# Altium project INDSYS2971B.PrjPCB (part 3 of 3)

## Sheet INDSYS2971B_DAC.SchDoc
size 431 x 279 mm; Date: Not shown in title block; ApprovedBy: Not shown in title block; CheckedBy: Not shown in title block; Author: Not shown in title block; CompanyName: Not shown in title block; Engineer: Not shown in title block; Organization: Not shown in title block; Address1: Not shown in title block; Address2: Not shown in title block; Address3: Not shown in title block; Address4: Not shown in title block; DocumentNumber: 8; Revision: Use project parameter SCH_Rev; SheetNumber: 8; SheetTotal: 11; PageSetup: Record=PageOptions¦CenterHorizontal=True¦CenterVertical=True¦PrintScale=1.00¦XCorrection=1.00¦YCorrection=1.00¦PrintKind=0¦BorderSize=5000000¦LeftOffset=0¦BottomOffset=0¦Orientation=2¦PaperLength=1000¦PaperWidth=1000¦Scale=100¦PaperSource=15¦PrintQuality=600¦MediaType=1¦DitherType=10¦PaperKind=Letter¦PrintScaleMode=1
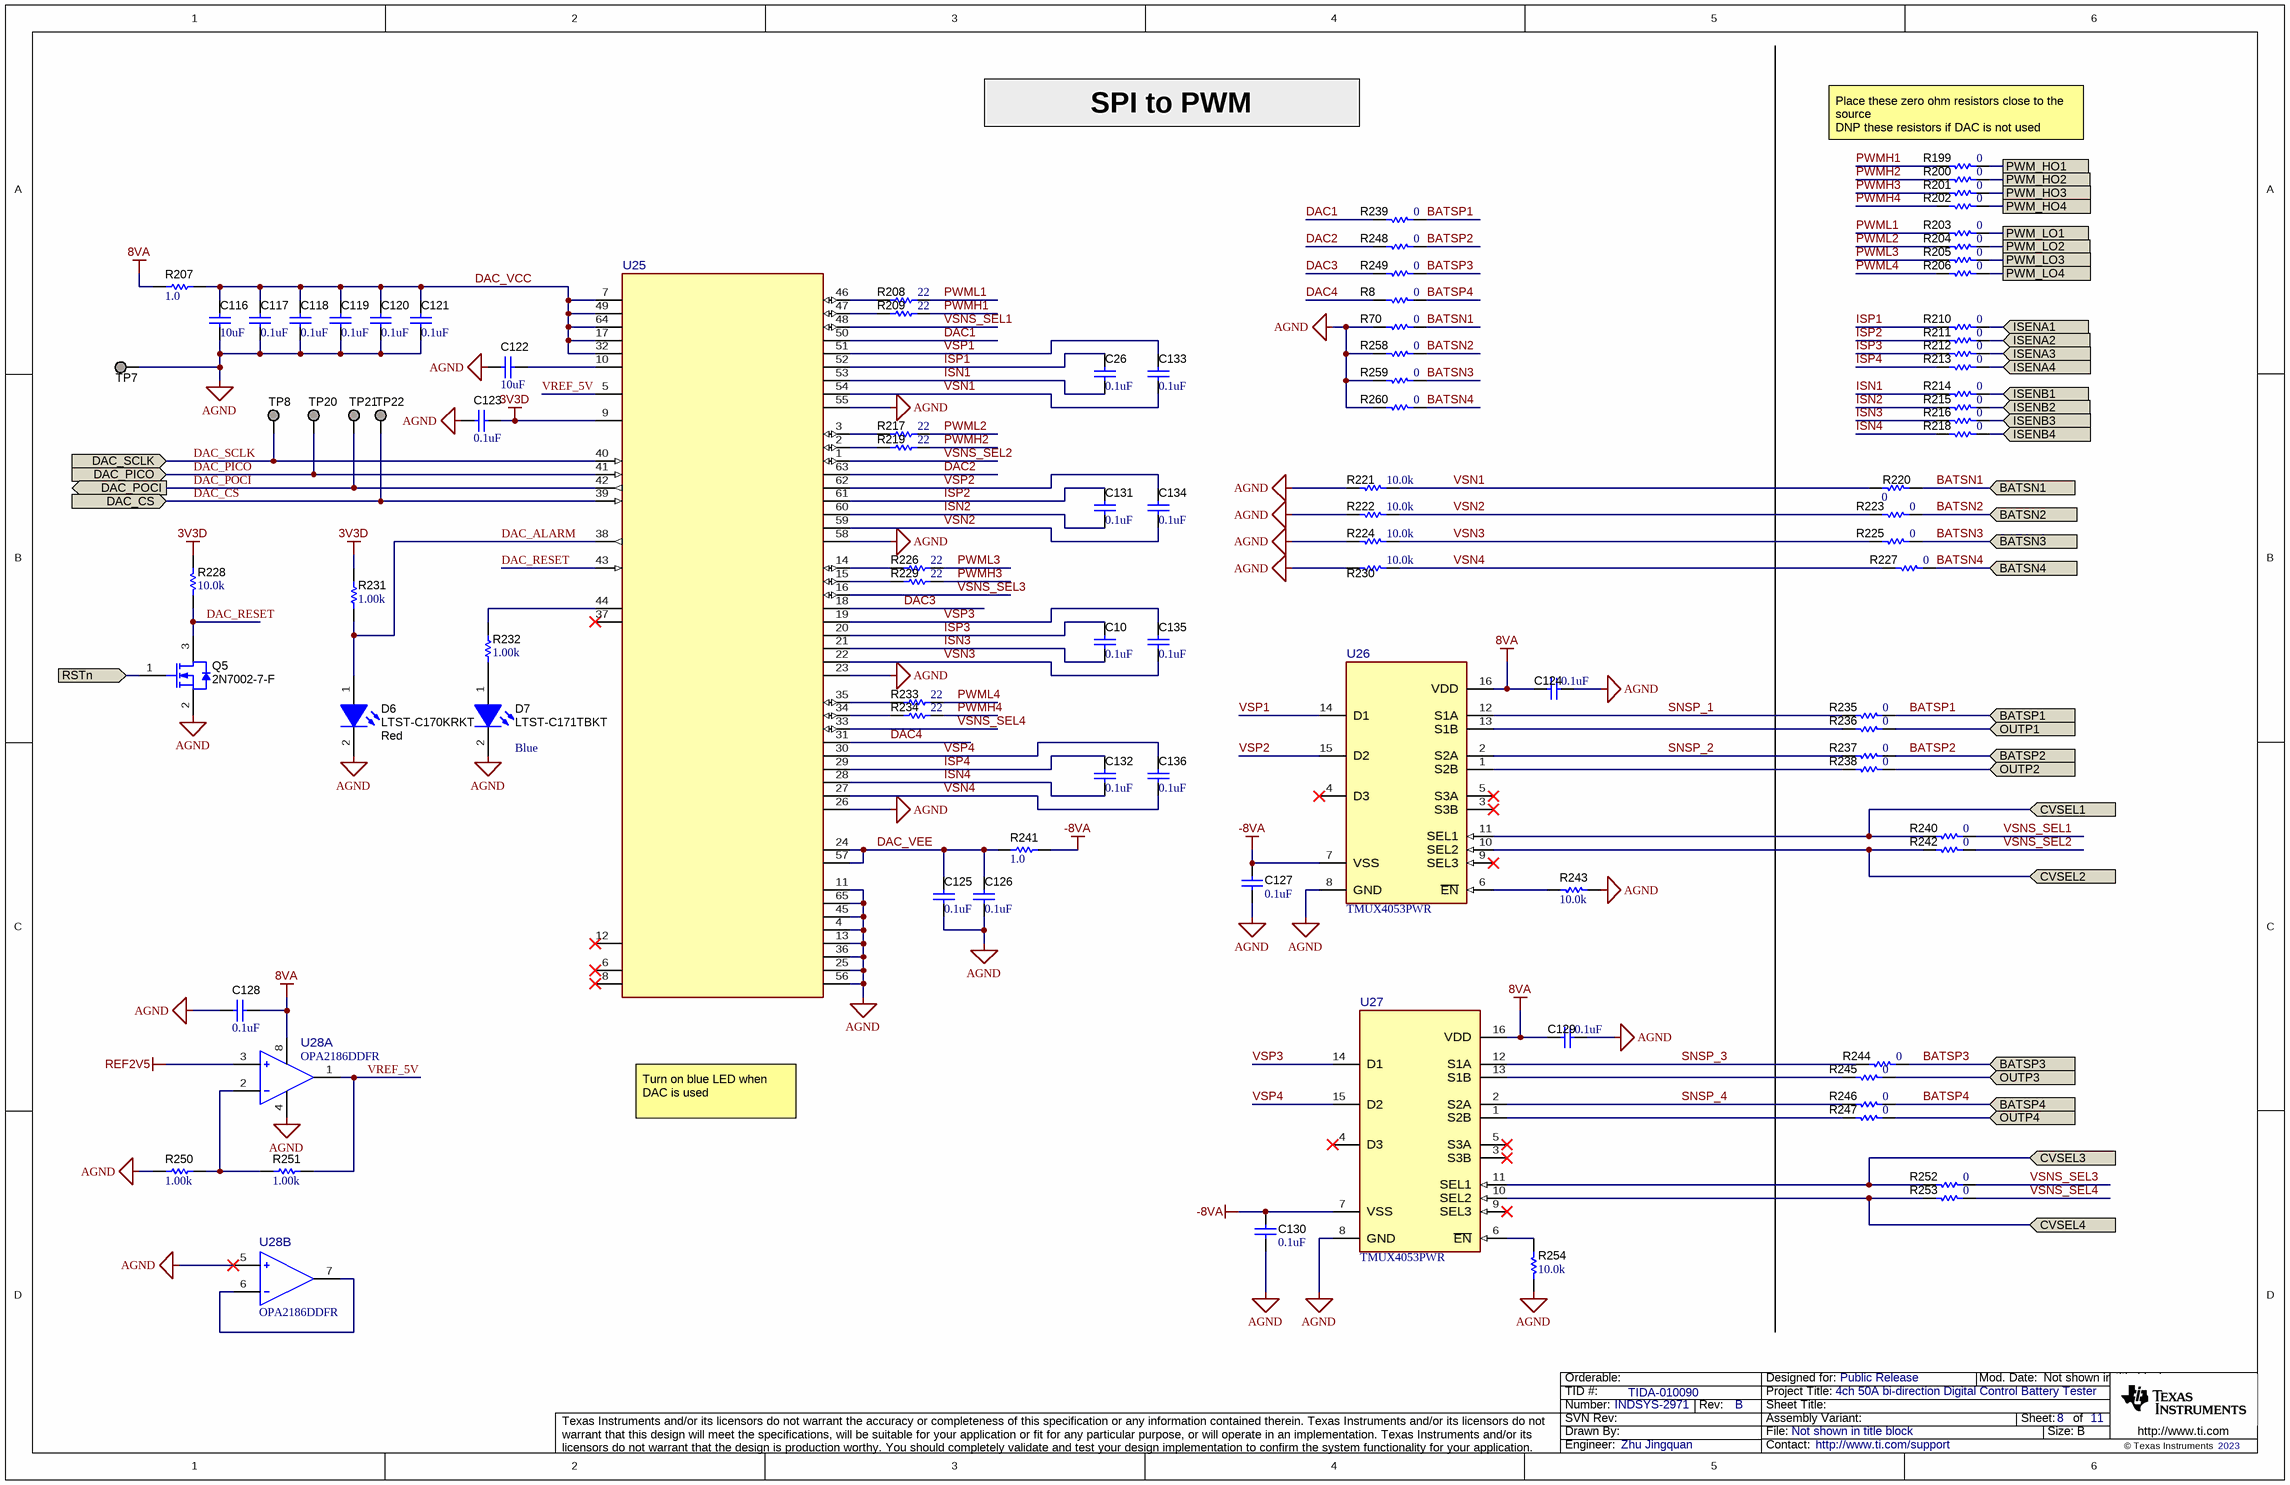
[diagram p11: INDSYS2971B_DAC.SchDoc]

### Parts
C10  ValueDisplayed: 0.1uF  [0402]  (hidden comment: GRM155R61C104KA88D)
C26  ValueDisplayed: 0.1uF  [0402]  (hidden comment: GRM155R61C104KA88D)
C116  ValueDisplayed: 10uF  [0603]  (hidden comment: GRM188R61E106MA73D)
C117  ValueDisplayed: 0.1uF  [0402]  (hidden comment: GRM155R61C104KA88D)
C118  ValueDisplayed: 0.1uF  [0402]  (hidden comment: GRM155R61C104KA88D)
C119  ValueDisplayed: 0.1uF  [0402]  (hidden comment: GRM155R61C104KA88D)
C120  ValueDisplayed: 0.1uF  [0402]  (hidden comment: GRM155R61C104KA88D)
C121  ValueDisplayed: 0.1uF  [0402]  (hidden comment: GRM155R61C104KA88D)
C122  ValueDisplayed: 10uF  [0603]  (hidden comment: GRM188R61E106MA73D)
C123  ValueDisplayed: 0.1uF  [0402]  (hidden comment: GRM155R61C104KA88D)
C124  ValueDisplayed: 0.1uF  [0402]  (hidden comment: GRM155R61C104KA88D)
C125  ValueDisplayed: 0.1uF  [0402]  (hidden comment: GRM155R61C104KA88D)
C126  ValueDisplayed: 0.1uF  [0402]  (hidden comment: GRM155R61C104KA88D)
C127  ValueDisplayed: 0.1uF  [0402]  (hidden comment: GRM155R61C104KA88D)
C128  ValueDisplayed: 0.1uF  [0402]  (hidden comment: GRM155R61C104KA88D)
C129  ValueDisplayed: 0.1uF  [0402]  (hidden comment: GRM155R61C104KA88D)
C130  ValueDisplayed: 0.1uF  [0402]  (hidden comment: GRM155R61C104KA88D)
C131  ValueDisplayed: 0.1uF  [0402]  (hidden comment: GRM155R61C104KA88D)
C132  ValueDisplayed: 0.1uF  [0402]  (hidden comment: GRM155R61C104KA88D)
C133  ValueDisplayed: 0.1uF  [0402]  (hidden comment: GRM155R61C104KA88D)
C134  ValueDisplayed: 0.1uF  [0402]  (hidden comment: GRM155R61C104KA88D)
C135  ValueDisplayed: 0.1uF  [0402]  (hidden comment: GRM155R61C104KA88D)
C136  ValueDisplayed: 0.1uF  [0402]  (hidden comment: GRM155R61C104KA88D)
D6  LTST-C170KRKT  value Red  [LED_LTST-C170_Red]
D7  LTST-C171TBKT  value Blue  [LTST-C171_Blue]
Q5  2N7002-7-F  [SOT-23]
R8  ValueDisplayed: 0  [0402]  (hidden comment: CRCW04020000Z0ED)
R70  ValueDisplayed: 0  [0402]  (hidden comment: CRCW04020000Z0ED)
R199  ValueDisplayed: 0  [0402]  (hidden comment: CRCW04020000Z0ED)
R200  ValueDisplayed: 0  [0402]  (hidden comment: CRCW04020000Z0ED)
R201  ValueDisplayed: 0  [0402]  (hidden comment: CRCW04020000Z0ED)
R202  ValueDisplayed: 0  [0402]  (hidden comment: CRCW04020000Z0ED)
R203  ValueDisplayed: 0  [0402]  (hidden comment: CRCW04020000Z0ED)
R204  ValueDisplayed: 0  [0402]  (hidden comment: CRCW04020000Z0ED)
R205  ValueDisplayed: 0  [0402]  (hidden comment: CRCW04020000Z0ED)
R206  ValueDisplayed: 0  [0402]  (hidden comment: CRCW04020000Z0ED)
R207  ValueDisplayed: 1.0  [0603]  (hidden comment: CRCW06031R00JNEA)
R208  ValueDisplayed: 22  [0402]  (hidden comment: CRCW040222R0JNED)
R209  ValueDisplayed: 22  [0402]  (hidden comment: CRCW040222R0JNED)
R210  ValueDisplayed: 0  [0402]  (hidden comment: CRCW04020000Z0ED)
R211  ValueDisplayed: 0  [0402]  (hidden comment: CRCW04020000Z0ED)
R212  ValueDisplayed: 0  [0402]  (hidden comment: CRCW04020000Z0ED)
R213  ValueDisplayed: 0  [0402]  (hidden comment: CRCW04020000Z0ED)
R214  ValueDisplayed: 0  [0402]  (hidden comment: CRCW04020000Z0ED)
R215  ValueDisplayed: 0  [0402]  (hidden comment: CRCW04020000Z0ED)
R216  ValueDisplayed: 0  [0402]  (hidden comment: CRCW04020000Z0ED)
R217  ValueDisplayed: 22  [0402]  (hidden comment: CRCW040222R0JNED)
R218  ValueDisplayed: 0  [0402]  (hidden comment: CRCW04020000Z0ED)
R219  ValueDisplayed: 22  [0402]  (hidden comment: CRCW040222R0JNED)
R220  ValueDisplayed: 0  [0402]  (hidden comment: CRCW04020000Z0ED)
R221  ValueDisplayed: 10.0k  [0402]  (hidden comment: PCF0402-12-10K0BT1)
R222  ValueDisplayed: 10.0k  [0402]  (hidden comment: PCF0402-12-10K0BT1)
R223  ValueDisplayed: 0  [0402]  (hidden comment: CRCW04020000Z0ED)
R224  ValueDisplayed: 10.0k  [0402]  (hidden comment: PCF0402-12-10K0BT1)
R225  ValueDisplayed: 0  [0402]  (hidden comment: CRCW04020000Z0ED)
R226  ValueDisplayed: 22  [0402]  (hidden comment: CRCW040222R0JNED)
R227  ValueDisplayed: 0  [0402]  (hidden comment: CRCW04020000Z0ED)
R228  ValueDisplayed: 10.0k  [0402]  (hidden comment: PCF0402-12-10K0BT1)
R229  ValueDisplayed: 22  [0402]  (hidden comment: CRCW040222R0JNED)
R230  ValueDisplayed: 10.0k  [0402]  (hidden comment: PCF0402-12-10K0BT1)
R231  ValueDisplayed: 1.00k  [0402]  (hidden comment: ERA-2AEB102X)
R232  ValueDisplayed: 1.00k  [0402]  (hidden comment: ERA-2AEB102X)
R233  ValueDisplayed: 22  [0402]  (hidden comment: CRCW040222R0JNED)
R234  ValueDisplayed: 22  [0402]  (hidden comment: CRCW040222R0JNED)
R235  ValueDisplayed: 0  [0402]  (hidden comment: CRCW04020000Z0ED)
R236  ValueDisplayed: 0  [0402]  (hidden comment: CRCW04020000Z0ED)
R237  ValueDisplayed: 0  [0402]  (hidden comment: CRCW04020000Z0ED)
R238  ValueDisplayed: 0  [0402]  (hidden comment: CRCW04020000Z0ED)
R239  ValueDisplayed: 0  [0402]  (hidden comment: CRCW04020000Z0ED)
R240  ValueDisplayed: 0  [0402]  (hidden comment: CRCW04020000Z0ED)
R241  ValueDisplayed: 1.0  [0603]  (hidden comment: CRCW06031R00JNEA)
R242  ValueDisplayed: 0  [0402]  (hidden comment: CRCW04020000Z0ED)
R243  ValueDisplayed: 10.0k  [0402]  (hidden comment: PCF0402-12-10K0BT1)
R244  ValueDisplayed: 0  [0402]  (hidden comment: CRCW04020000Z0ED)
R245  ValueDisplayed: 0  [0402]  (hidden comment: CRCW04020000Z0ED)
R246  ValueDisplayed: 0  [0402]  (hidden comment: CRCW04020000Z0ED)
R247  ValueDisplayed: 0  [0402]  (hidden comment: CRCW04020000Z0ED)
R248  ValueDisplayed: 0  [0402]  (hidden comment: CRCW04020000Z0ED)
R249  ValueDisplayed: 0  [0402]  (hidden comment: CRCW04020000Z0ED)
R250  ValueDisplayed: 1.00k  [0402]  (hidden comment: ERA-2AEB102X)
R251  ValueDisplayed: 1.00k  [0402]  (hidden comment: ERA-2AEB102X)
R252  ValueDisplayed: 0  [0402]  (hidden comment: CRCW04020000Z0ED)
R253  ValueDisplayed: 0  [0402]  (hidden comment: CRCW04020000Z0ED)
R254  ValueDisplayed: 10.0k  [0402]  (hidden comment: PCF0402-12-10K0BT1)
R258  ValueDisplayed: 0  [0402]  (hidden comment: CRCW04020000Z0ED)
R259  ValueDisplayed: 0  [0402]  (hidden comment: CRCW04020000Z0ED)
R260  ValueDisplayed: 0  [0402]  (hidden comment: CRCW04020000Z0ED)
TP7  5019  [Keystone_5019]  (value not drawn)
TP8  5019  [Keystone_5019]  (value not drawn)
TP20  5019  [Keystone_5019]  (value not drawn)
TP21  5019  [Keystone_5019]  (value not drawn)
TP22  5019  [Keystone_5019]  (value not drawn)
U25  (no value)  [RGC0064P-MFG]
U26  TMUX4053PWR  [PW0016A-MFG]
U27  TMUX4053PWR  [PW0016A-MFG]
U28  OPA2186DDFR  [DDF0008A-MFG]  (parts A,B of 2)

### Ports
BATSN1 (in), BATSN2 (in), BATSN3 (in), BATSN4 (in), BATSP1 (in), BATSP2 (in), BATSP3 (in), BATSP4 (in), CVSEL1 (in), CVSEL2 (in), CVSEL3 (in), CVSEL4 (in), DAC_CS (in), DAC_PICO (in), DAC_POCI (out), DAC_SCLK (in), ISENA1 (in), ISENA2 (in), ISENA3 (in), ISENA4 (in), ISENB1 (in), ISENB2 (in), ISENB3 (in), ISENB4 (in), OUTP1 (in), OUTP2 (in), OUTP3 (in), OUTP4 (in), PWM_HO1, PWM_HO2, PWM_HO3, PWM_HO4, PWM_LO1, PWM_LO2, PWM_LO3, PWM_LO4, RSTn (in)

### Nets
3V3D: C123.2 R228.2 R231.2 U25.9(NC)
8VA: C124.2 C128.1 C129.2 R207.1 U26.16(VDD) U27.16(VDD) U28.8(V+)
-8VA: C127.2 C130.2 R241.2 U26.7(VSS) U27.7(VSS)
AGND: C116.2 C117.1 C118.1 C119.1 C120.1 C121.1 C122.1 C123.1 C124.1 C125.1 C126.1 C127.1 C128.2 C129.1 C130.1 D6.2(K) D7.2(K) Q5.2(S) R70.2 R221.1 R222.1 R224.1 R230.1 R243.1 R250.1 R254.1 R258.2 R259.2 R260.2 TP7.1 U25.4(NC) U25.11(NC) U25.13(NC) U25.23(NC) U25.25(NC) U25.26(NC) U25.36(NC) U25.45(NC) U25.55(NC) U25.56(NC) U25.58(NC) U25.65(NC) U26.8(GND) U27.8(GND) U28.4(V-) U28.5(+IN_B)
REF2V5: U28.3(+IN_A)
BATSN1: R70.1 R220.1 ; port BATSN1
BATSN2: R223.1 R258.1 ; port BATSN2
BATSN3: R225.1 R259.1 ; port BATSN3
BATSN4: R227.1 R260.1 ; port BATSN4
BATSP1: R235.1 R239.1 ; port BATSP1
BATSP2: R237.1 R248.1 ; port BATSP2
BATSP3: R244.1 R249.1 ; port BATSP3
BATSP4: R8.1 R246.1 ; port BATSP4
CVSEL1: R240.2 U26.11(SEL1) ; port CVSEL1
CVSEL2: R242.2 U26.10(SEL2) ; port CVSEL2
CVSEL3: R252.2 U27.11(SEL1) ; port CVSEL3
CVSEL4: R253.2 U27.10(SEL2) ; port CVSEL4
DAC1: R239.2 U25.50(NC)
DAC2: R248.2 U25.63(NC)
DAC3: R249.2 U25.18(NC)
DAC4: R8.2 U25.31(NC)
DAC_ALARM: D6.1(A) R231.1 U25.38(NC)
DAC_CS: TP22.1 U25.39(NC) ; port DAC_CS
DAC_PICO: TP20.1 U25.41(NC) ; port DAC_PICO
DAC_POCI: TP21.1 U25.42(NC) ; port DAC_POCI
DAC_RESET: Q5.3(D) R228.1 U25.43(NC)
DAC_SCLK: TP8.1 U25.40(NC) ; port DAC_SCLK
DAC_VCC: C116.1 C117.2 C118.2 C119.2 C120.2 C121.2 R207.2 U25.7(NC) U25.17(NC) U25.32(NC) U25.49(NC) U25.64(NC)
DAC_VEE: C125.2 C126.2 R241.1 U25.24(NC) U25.57(NC)
ISENA1: R210.1 ; port ISENA1
ISENA2: R211.1 ; port ISENA2
ISENA3: R212.1 ; port ISENA3
ISENA4: R213.1 ; port ISENA4
ISENB1: R214.1 ; port ISENB1
ISENB2: R215.1 ; port ISENB2
ISENB3: R216.1 ; port ISENB3
ISENB4: R218.1 ; port ISENB4
ISN1: C26.1 R214.2 U25.53(NC)
ISN2: C131.1 R215.2 U25.60(NC)
ISN3: C10.1 R216.2 U25.21(NC)
ISN4: C132.1 R218.2 U25.28(NC)
ISP1: C26.2 R210.2 U25.52(NC)
ISP2: C131.2 R211.2 U25.61(NC)
ISP3: C10.2 R212.2 U25.20(NC)
ISP4: C132.2 R213.2 U25.29(NC)
OUTP1: R236.1 ; port OUTP1
OUTP2: R238.1 ; port OUTP2
OUTP3: R245.1 ; port OUTP3
OUTP4: R247.1 ; port OUTP4
PWM_HO1: R199.1 ; port PWM_HO1
PWM_HO2: R200.1 ; port PWM_HO2
PWM_HO3: R201.1 ; port PWM_HO3
PWM_HO4: R202.1 ; port PWM_HO4
PWM_LO1: R203.1 ; port PWM_LO1
PWM_LO2: R204.1 ; port PWM_LO2
PWM_LO3: R205.1 ; port PWM_LO3
PWM_LO4: R206.1 ; port PWM_LO4
PWMH1: R199.2 R209.2
PWMH2: R200.2 R219.2
PWMH3: R201.2 R229.2
PWMH4: R202.2 R234.2
PWML1: R203.2 R208.2
PWML2: R204.2 R217.2
PWML3: R205.2 R226.2
PWML4: R206.2 R233.2
RSTn: Q5.1(G) ; port RSTn
SNSP_1: R235.2 U26.12(S1A)
SNSP_2: R237.2 U26.2(S2A)
SNSP_3: R244.2 U27.12(S1A)
SNSP_4: R246.2 U27.2(S2A)
VREF_5V: R251.2 U25.5(NC) U28.1(OUT_A)
VSN1: C133.1 R220.2 R221.2 U25.54(NC)
VSN2: C134.1 R222.2 R223.2 U25.59(NC)
VSN3: C135.1 R224.2 R225.2 U25.22(NC)
VSN4: C136.1 R227.2 R230.2 U25.27(NC)
VSNS_SEL1: R240.1 U25.48(NC)
VSNS_SEL2: R242.1 U25.1(HARTB/GPIO2B)
VSNS_SEL3: R252.1 U25.16(NC)
VSNS_SEL4: R253.1 U25.33(NC)
VSP1: C133.2 U25.51(NC) U26.14(D1)
VSP2: C134.2 U25.62(NC) U26.15(D2)
VSP3: C135.2 U25.19(NC) U27.14(D1)
VSP4: C136.2 U25.30(NC) U27.15(D2)
NetC122_2: C122.2 U25.10(NC)
NetD7_1: D7.1(A) R232.1
NetR208_1: R208.1 U25.46(NC)
NetR209_1: R209.1 U25.47(NC)
NetR217_1: R217.1 U25.3(GPIO0B)
NetR219_1: R219.1 U25.2(PPCB/GPIO1B)
NetR226_1: R226.1 U25.14(NC)
NetR229_1: R229.1 U25.15(NC)
NetR232_2: R232.2 U25.44(NC)
NetR233_1: R233.1 U25.35(NC)
NetR234_1: R234.1 U25.34(NC)
NetR236_2: R236.2 U26.13(S1B)
NetR238_2: R238.2 U26.1(S2B)
NetR243_2: R243.2 U26.6(~{EN})
NetR245_2: R245.2 U27.13(S1B)
NetR247_2: R247.2 U27.1(S2B)
NetR250_2: R250.2 R251.1 U28.2(-IN_A)
NetR254_2: R254.2 U27.6(~{EN})
NetU28_6: U28.6(-IN_B) U28.7(OUT_B)

Not connected (* = marked no-connect by the designer): U25 6(NC)* 8(NC)* 12(NC)* 37(NC)*; U26 3(S3B)* 4(D3)* 5(S3A)* 9(SEL3)*; U27 3(S3B)* 4(D3)* 5(S3A)* 9(SEL3)*

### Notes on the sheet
- SPI to PWM
- Place these zero ohm resistors close to the source
  DNP these resistors if DAC is not used
- Turn on blue LED when DAC is used

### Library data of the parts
C10 C26 C117-C121 C123-C136 = CMP-0006591-2: CAP, CERM, 0.1 uF, 16 V, +/- 10%, X5R, 0402; Manufacturer: MuRata; TaMin_C: -55°C; Polarized: N; SizeAreaWB_mm2: 3; Value1: Unknown; U/M: EA; Value: 0.1uF; TaMax_C: 85°C; SizeZ_mm: 0.6; SizeX_mm: 1; SizeY_mm: 0.5; Value2: 16V; Cap_F: 100nF; AEC Category: Q200
C116 C122 = CMP-0007344-5: CAP, CERM, 10 uF, 25 V, +/- 20%, X5R, 0603; Manufacturer: MuRata; Polarized: N; Value: 10uF; U/M: EA; Cap_F: 10µF; Value1: Unknown; VDC_V: 25V; TaMin_C: -55°C; TaMax_C: 85°C; SizeArea_mm2: 1.28; SizeAreaWB_mm2: 4.68; SizeX_mm: 1.6; SizeY_mm: 0.8; SizeZ_mm: 1; AEC Category: Q200
D6 = CMP-0002829-3: LED, Red, SMD; Manufacturer: Lite-On; SizeZ_mm: 1.2; Value1: W; SizeY_mm: 1.25; Value2: 2V; SizeArea_mm2: 2.5; SizeX_mm: 2; SizeAreaWB_mm2: 6.75; Io_A: 20mA; Type: AlInGaP
D7 = CMP-0082437-2: LED, Blue, SMD; Manufacturer: Lite-On; Vr_V: 5V; SizeArea_mm2: 2.5; SizeAreaWB_mm2: 6.75; Io_A: 20mA; Green_Lifecycle: Not Set; Angle: 130; Value1: 0.076W; Type: InGaN; SizeY_mm: 1.25; Ir_A: 10µA; Power_TotalModule: 76mW; Value2: 3.3V; Green_REACh: Incomplete; SizeX_mm: 2; SizeZ_mm: 0.9
Q5 = CMP-0000769-1: MOSFET, N-CH, 60 V, 0.17 A, SOT-23; Alternate Manufacturer: None; Manufacturer: Diodes Inc.; SizeZ_mm: 1.1; ChType: N; Value2: 223 nC; Value1: 7; VdsMax_V: 60V; SizeX_mm: 2.5; SizeY_mm: 3; Vgs_V: 20V; Value: 60V; Rdson45_ohm: 7.5; AEC Category: Q101; IdsMax_A: 170mA; SizeAreaWB_mm2: 14; U/M: EA; QgTyp_nC: 223
R8 R70 R199-R206 R210-R216 R218 R220 R223 R225 R227 R235-R240 R242 R244-R249 R252 R253 R258-R260 = CMP-0026822-3: RES, 0, 5%, 0.063 W, AEC-Q200 Grade 0, 0402; Manufacturer: Vishay-Dale; Value: 0; Value_Code: 0000; Power_W: 63mW; Value2: 0.063W; VDC_V: 50V; TempCo: 200 ppm/C; SizeArea_mm2: 0.5; SizeX_mm: 1; SizeZ_mm: 0.6; EIA_Code: E24; AEC Category: Q200; AEC Qualified: Y
R207 R241 = CMP-0025743-4: RES, 1.0, 5%, 0.1 W, AEC-Q200 Grade 0, 0603; Manufacturer: Vishay-Dale; Power_W: 100mW; TempCo: 200 ppm/C; Value_Code: 1R00; Value: 1.0; EIA_Code: E24; Res_ohm: 1; SizeX_mm: 1.6; SizeY_mm: 0.8; Value2: 0.1W; SizeArea_mm2: 1.28; AEC Qualified: Y; VDC_V: 75V; AEC Category: Q200; AEC Grade: 0
R208 R209 R217 R219 R226 R229 R233 R234 = CMP-0026880-3: RES, 22, 5%, 0.063 W, AEC-Q200 Grade 0, 0402; Manufacturer: Vishay-Dale; Power_W: 63mW; TempCo: 200 ppm/C; Value_Code: 22R0; Value: 22; EIA_Code: E24; SizeX_mm: 1; SizeY_mm: 0.5; SizeZ_mm: 0.6; Value2: 0.063W; AEC Qualified: Y; VDC_V: 50V; AEC Category: Q200; AEC Grade: 0
R221 R222 R224 R228 R230 R243 R254 = CMP-0026796-1: RES, 10.0 k, 0.1%, 0.063 W, 0402; Manufacturer: TT Electronics/IRC; Power_W: 63mW; TempCo: 10 ppm/C; Value_Code: 10k0; U/M: EA; Value: 10.0k; EIA_Code: E192; Res_ohm: 10k; SizeX_mm: 1; SizeY_mm: 0.5; SizeZ_mm: 0.6; Value2: 0.063W; AEC Qualified: N; VDC_V: 25V; AEC Category: Q200
R231 R232 R250 R251 = CMP-0026770-1: RES, 1.00 k, 0.1%, 0.063 W, 0402; Manufacturer: Panasonic; Power_W: 63mW; TempCo: 25 ppm/C; Value_Code: 1k00; U/M: EA; Value: 1.00k; EIA_Code: E192; Res_ohm: 1k; SizeX_mm: 1; SizeY_mm: 0.5; SizeZ_mm: 0.6; Value2: 0.063W; VDC_V: 50V; AEC Category: Q200
TP7 TP8 TP20-TP22 = CMP-0055162-1: Test Point, Miniature, SMT; Manufacturer: Keystone; CNHeader: FALSE; Green_Lifecycle: Active; Green_REACh: Passed; CT: TRUE
U25 = CMP-0049649-2: Manufacturer: Texas Instruments; PartNumber: NA; SizeZ_mm: 1mm; AEC Qualified: No; Standoff Height: 0mm; TaMax_C: +125°C; TaMin_C: -40°C; TJmax_C: +150°C
U26 U27 = CMP-0043042-1: +/-12-V, 2:1, 3-channel multiplexer with 1.8-V logic compatible logic; Manufacturer: Texas Instruments; SizeZ_mm: 1.2mm; AEC Qualified: No; -3Db Bandwith: 850MHz; Max Supply Voltage: 24V; Min Supply Voltage: 5V; On State Resistance: 60Ω; PositionCount: 3; Standoff Height: 0.05mm; TaMax_C: +125°C; TaMin_C: -55°C; TJmax_C: +150°C
U28 = CMP-0098326-1: Precision, Rail-to-Rail Input and Output, 24-V, Zero-Drift Operational Amplifiers; Manufacturer: Texas Instruments; SizeZ_mm: 1.1mm; AEC Qualified: No; Gain Bandwidth: 750kHz; Input Bias Current: 0.000005uA; Input Offset Voltage: 0.001mV; Max Dual Supply Voltage: 12V; Max Supply Voltage: 24V; Min Dual Supply Voltage: 2.25V; Min Supply Voltage: 4.5V; Nominal Supply Current: 90uA; Number Of Channels: 2; Output Current Per Channel: 20mA; Response Time: 7.5us; Standoff Height: 0mm; TaMax_C: +125°C; TaMin_C: -40°C; TJmax_C: +150°C; Voltage Gain: 148dB

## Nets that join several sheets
3V3A: INDSYS2971B_SAR_ADC (C69.1 U13.4), INDSYS2971B_BiasPower (C85.1 R126.2 U17.5), INDSYS2971B_CurrentSense (C109.2 U23.4), INDSYS2971B_VoltageSense (C96.2 U21.4)
3V3D: INDSYS2971B_SAR_ADC (11 pins), INDSYS2971B_BiasPower (C94.1 R128.1 R131.2 U19.5), INDSYS2971B_ControlCard (C39.2 U8.8), INDSYS2971B_DAC (C123.2 R228.2 R231.2 U25.9)
5VA: 1 (C30_1.2 C31_1.2 R23_1.1 U6_1.3), 2 (C30_2.2 C31_2.2 R23_2.1 U6_2.3), 3 (C30_3.2 C31_3.2 R23_3.1 U6_3.3), 4 (C30_4.2 C31_4.2 R23_4.1 U6_4.3), INDSYS2971B_SAR_ADC (C60.1 R88.1 U11.1 U11.2), INDSYS2971B_BiasPower (6 pins), INDSYS2971B_ControlCard (C40.2 U9.4)
5VD: 1 (7 pins), 2 (7 pins), 3 (7 pins), 4 (7 pins), INDSYS2971B_BiasPower (5 pins), INDSYS2971B_ControlCard (10 pins)
8VA: 1 (C29_1.1 R34_1.1 U7_1.8), 2 (C29_2.1 R34_2.1 U7_2.8), 3 (C29_3.1 R34_3.1 U7_3.8), 4 (C29_4.1 R34_4.1 U7_4.8), INDSYS2971B_BiasPower (7 pins), INDSYS2971B_CurrentSense (8 pins), INDSYS2971B_VoltageSense (C98.2 C104.2 U20.8 U22.8), INDSYS2971B_DAC (7 pins)
-8VA: 1 (C33_1.1 R27_1.1 U7_1.4), 2 (C33_2.1 R27_2.1 U7_2.4), 3 (C33_3.1 R27_3.1 U7_3.4), 4 (C33_4.1 R27_4.1 U7_4.4), INDSYS2971B_BiasPower (J17.1), INDSYS2971B_CurrentSense (12 pins), INDSYS2971B_VoltageSense (C99.2 C105.2 U20.4 U22.4), INDSYS2971B_DAC (5 pins)
AGND: INDSYS2971B (J6.1 J6.2 J6.3), 1 (13 pins), 2 (13 pins), 3 (13 pins), 4 (13 pins), 1 (10 pins), 2 (10 pins), 3 (10 pins), 4 (10 pins), INDSYS2971B_SAR_ADC (36 pins), INDSYS2971B_BiasPower (24 pins), INDSYS2971B_ControlCard (28 pins), INDSYS2971B_CurrentSense (26 pins), INDSYS2971B_VoltageSense (18 pins), INDSYS2971B_DAC (46 pins)
PGND: INDSYS2971B (5 pins), 1 (21 pins), 2 (21 pins), 3 (21 pins), 4 (21 pins), 1 (8 pins), 2 (8 pins), 3 (8 pins), 4 (8 pins), INDSYS2971B_BiasPower (23 pins), INDSYS2971B_VoltageSense (8 pins)
REF1V25: INDSYS2971B_SAR_ADC (U13.1 U13.2), INDSYS2971B_CurrentSense (R177.2 R178.2 R185.2 R186.2)
REF2V5: INDSYS2971B_SAR_ADC (5 pins), INDSYS2971B_DAC (U28.3)
REF2V5_C2K: INDSYS2971B_SAR_ADC (C68.2 R111.2 R113.1), INDSYS2971B_ControlCard (R36.1 R46.2)
BATSN1: 1 (J10_1.1 R22_1.2), INDSYS2971B_VoltageSense (R136.1 R138.2), INDSYS2971B_DAC (R70.1 R220.1)
BATSN2: 2 (J10_2.1 R22_2.2), INDSYS2971B_VoltageSense (R147.1 R149.2), INDSYS2971B_DAC (R223.1 R258.1)
BATSN3: 3 (J10_3.1 R22_3.2), INDSYS2971B_VoltageSense (R159.1 R161.2), INDSYS2971B_DAC (R225.1 R259.1)
BATSN4: 4 (J10_4.1 R22_4.2), INDSYS2971B_VoltageSense (R172.1 R173.2), INDSYS2971B_DAC (R227.1 R260.1)
BATSP1: 1 (J10_1.2 R19_1.2 R24_1.1), INDSYS2971B_VoltageSense (R133.2 R135.1), INDSYS2971B_DAC (R235.1 R239.1)
BATSP2: 2 (J10_2.2 R19_2.2 R24_2.1), INDSYS2971B_VoltageSense (R144.2 R146.1), INDSYS2971B_DAC (R237.1 R248.1)
BATSP3: 3 (J10_3.2 R19_3.2 R24_3.1), INDSYS2971B_VoltageSense (R155.2 R157.1), INDSYS2971B_DAC (R244.1 R249.1)
BATSP4: 4 (J10_4.2 R19_4.2 R24_4.1), INDSYS2971B_VoltageSense (R166.2 R170.1), INDSYS2971B_DAC (R8.1 R246.1)
BUSY_INT: INDSYS2971B_SAR_ADC (U10.14), INDSYS2971B_ControlCard (R68.1)
CSn: INDSYS2971B_SAR_ADC (R92.2 U10.13), INDSYS2971B_ControlCard (R63.1)
CVSEL1: INDSYS2971B_ControlCard (R195.1), INDSYS2971B_DAC (R240.2 U26.11)
CVSEL2: INDSYS2971B_ControlCard (R197.1), INDSYS2971B_DAC (R242.2 U26.10)
CVSEL3: INDSYS2971B_ControlCard (R196.2), INDSYS2971B_DAC (R252.2 U27.11)
CVSEL4: INDSYS2971B_ControlCard (R198.2), INDSYS2971B_DAC (R253.2 U27.10)
DAC_CS: INDSYS2971B_ControlCard (R67.1), INDSYS2971B_DAC (TP22.1 U25.39)
DAC_PICO: INDSYS2971B_ControlCard (R65.1), INDSYS2971B_DAC (TP20.1 U25.41)
DAC_POCI: INDSYS2971B_ControlCard (R194.1), INDSYS2971B_DAC (TP21.1 U25.42)
DAC_SCLK: INDSYS2971B_ControlCard (R66.1), INDSYS2971B_DAC (TP8.1 U25.40)
EN_SSR1: 1 (R31_1.1 R32_1.1), INDSYS2971B_ControlCard (R72.1)
EN_SSR2: 2 (R31_2.1 R32_2.1), INDSYS2971B_ControlCard (R73.1)
EN_SSR3: 3 (R31_3.1 R32_3.1), INDSYS2971B_ControlCard (R74.1)
EN_SSR4: 4 (R31_4.1 R32_4.1), INDSYS2971B_ControlCard (R75.1)
IOCP1: INDSYS2971B_ControlCard (R37.2), INDSYS2971B_CurrentSense (C111.1 R184.1 U23.1)
IOCP2: INDSYS2971B_ControlCard (R39.2), INDSYS2971B_CurrentSense (C110.1 R183.1 U23.7)
IOCP3: INDSYS2971B_ControlCard (R38.2), INDSYS2971B_CurrentSense (C113.1 R192.1 U23.8)
IOCP4: INDSYS2971B_ControlCard (R40.2), INDSYS2971B_CurrentSense (C112.1 R191.1 U23.14)
IoutN1: INDSYS2971B_SAR_ADC (R81.1), INDSYS2971B_CurrentSense (R16.2)
IoutN2: INDSYS2971B_SAR_ADC (R85.1), INDSYS2971B_CurrentSense (R255.2)
IoutN3: INDSYS2971B_SAR_ADC (R87.1), INDSYS2971B_CurrentSense (R256.2)
IoutN4: INDSYS2971B_SAR_ADC (R91.1), INDSYS2971B_CurrentSense (R257.2)
IoutP1: INDSYS2971B_SAR_ADC (R78.1), INDSYS2971B_CurrentSense (R180.1 U4.5)
IoutP2: INDSYS2971B_SAR_ADC (R83.1), INDSYS2971B_CurrentSense (R179.1 U12.5)
IoutP3: INDSYS2971B_SAR_ADC (R86.1), INDSYS2971B_CurrentSense (R187.1 U29.5)
IoutP4: INDSYS2971B_SAR_ADC (R90.1), INDSYS2971B_CurrentSense (R188.1 U30.5)
ISENA1: 1 (R4_1.1 R12_1.1), INDSYS2971B_CurrentSense (U4.8), INDSYS2971B_DAC (R210.1)
ISENA2: 2 (R4_2.1 R12_2.1), INDSYS2971B_CurrentSense (U12.8), INDSYS2971B_DAC (R211.1)
ISENA3: 3 (R4_3.1 R12_3.1), INDSYS2971B_CurrentSense (U29.8), INDSYS2971B_DAC (R212.1)
ISENA4: 4 (R4_4.1 R12_4.1), INDSYS2971B_CurrentSense (U30.8), INDSYS2971B_DAC (R213.1)
ISENB1: 1 (R5_1.1 R13_1.1), INDSYS2971B_CurrentSense (U4.1), INDSYS2971B_DAC (R214.1)
ISENB2: 2 (R5_2.1 R13_2.1), INDSYS2971B_CurrentSense (U12.1), INDSYS2971B_DAC (R215.1)
ISENB3: 3 (R5_3.1 R13_3.1), INDSYS2971B_CurrentSense (U29.1), INDSYS2971B_DAC (R216.1)
ISENB4: 4 (R5_4.1 R13_4.1), INDSYS2971B_CurrentSense (U30.1), INDSYS2971B_DAC (R218.1)
NetJ3_1: INDSYS2971B (J3.1), INDSYS2971B_ControlCard (R76.2 U8.7)
NetJ3_2: INDSYS2971B (J3.2), INDSYS2971B_ControlCard (R76.1 U8.6)
NetR54_2: INDSYS2971B (TP19.1), INDSYS2971B_ControlCard (R54.2)
NetR71_2: INDSYS2971B (TP18.1), INDSYS2971B_ControlCard (R71.2)
OUTP1: 1 (R2_1.3 R6_1.2), 1 (13 pins), INDSYS2971B_VoltageSense (R133.1 R140.1), INDSYS2971B_DAC (R236.1)
OUTP2: 2 (R2_2.3 R6_2.2), 2 (13 pins), INDSYS2971B_VoltageSense (R144.1 R152.1), INDSYS2971B_DAC (R238.1)
OUTP3: 3 (R2_3.3 R6_3.2), 3 (13 pins), INDSYS2971B_VoltageSense (R155.1 R160.1), INDSYS2971B_DAC (R245.1)
OUTP4: 4 (R2_4.3 R6_4.2), 4 (13 pins), INDSYS2971B_VoltageSense (R166.1 R169.1), INDSYS2971B_DAC (R247.1)
PWM_HO1: 1 (R11_1.1 U2_1.14), INDSYS2971B_ControlCard (R47.1), INDSYS2971B_DAC (R199.1)
PWM_HO2: 2 (R11_2.1 U2_2.14), INDSYS2971B_ControlCard (R51.1), INDSYS2971B_DAC (R200.1)
PWM_HO3: 3 (R11_3.1 U2_3.14), INDSYS2971B_ControlCard (R48.2), INDSYS2971B_DAC (R201.1)
PWM_HO4: 4 (R11_4.1 U2_4.14), INDSYS2971B_ControlCard (R55.2), INDSYS2971B_DAC (R202.1)
PWM_LO1: 1 (R10_1.1 U24_1.1 U24_1.3), INDSYS2971B_ControlCard (R49.1), INDSYS2971B_DAC (R203.1)
PWM_LO2: 2 (R10_2.1 U24_2.1 U24_2.3), INDSYS2971B_ControlCard (R53.1), INDSYS2971B_DAC (R204.1)
PWM_LO3: 3 (R10_3.1 U24_3.1 U24_3.3), INDSYS2971B_ControlCard (R50.2), INDSYS2971B_DAC (R205.1)
PWM_LO4: 4 (R10_4.1 U24_4.1 U24_4.3), INDSYS2971B_ControlCard (R56.2), INDSYS2971B_DAC (R206.1)
RSTn: INDSYS2971B_SAR_ADC (R84.1 U10.11), INDSYS2971B_ControlCard (R69.1), INDSYS2971B_DAC (Q5.1)
SCLK: INDSYS2971B_SAR_ADC (U10.12), INDSYS2971B_ControlCard (R61.1)
SDOA: INDSYS2971B_SAR_ADC (U10.24), INDSYS2971B_ControlCard (R59.1)
STARTA: INDSYS2971B_SAR_ADC (R89.1 U10.9 U10.10), INDSYS2971B_ControlCard (R52.2)
V_HV: INDSYS2971B (C1.1 J1.1 T1.1 TP1.1), 1 (F1_1.2), 2 (F1_2.2), 3 (F1_3.2), 4 (F1_4.2), INDSYS2971B_SAR_ADC (R115.2), INDSYS2971B_BiasPower (J16.3)
VbatN1: INDSYS2971B_SAR_ADC (R94.1), INDSYS2971B_VoltageSense (R139.2)
VbatN2: INDSYS2971B_SAR_ADC (R96.1), INDSYS2971B_VoltageSense (R151.2)
VbatN3: INDSYS2971B_SAR_ADC (R98.1), INDSYS2971B_VoltageSense (R162.2)
VbatN4: INDSYS2971B_SAR_ADC (R102.1), INDSYS2971B_VoltageSense (R175.2)
VbatP1: INDSYS2971B_SAR_ADC (R93.1), INDSYS2971B_VoltageSense (C97.2 R141.1 U20.1)
VbatP2: INDSYS2971B_SAR_ADC (R95.1), INDSYS2971B_VoltageSense (C101.2 R150.1 U20.7)
VbatP3: INDSYS2971B_SAR_ADC (R97.1), INDSYS2971B_VoltageSense (C103.2 R164.1 U22.1)
VbatP4: INDSYS2971B_SAR_ADC (R100.1), INDSYS2971B_VoltageSense (C108.2 R174.1 U22.7)
Vin: INDSYS2971B_SAR_ADC (U13.6 U13.7), INDSYS2971B_ControlCard (R41.2)
VoutP1: INDSYS2971B_ControlCard (R42.2), INDSYS2971B_VoltageSense (C100.2 R143.2 U21.1)
VoutP2: INDSYS2971B_ControlCard (R43.2), INDSYS2971B_VoltageSense (C102.2 R154.2 U21.7)
VoutP3: INDSYS2971B_ControlCard (R44.2), INDSYS2971B_VoltageSense (C106.2 R165.2 U21.8)
VoutP4: INDSYS2971B_ControlCard (R45.2), INDSYS2971B_VoltageSense (C107.2 R176.2 U21.14)

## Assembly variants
001: not fitted C10 C18_1 C18_2 C18_3 C18_4 C24_1 C24_2 C24_3 C24_4 C26 C28_1 C28_2 C28_3 C28_4 C97 C100 C101 C102 C103 C106 C107 C108 C114_1 C114_2 C114_3 C114_4 C131 C132 C133 C134 C135 C136 D4_1 D4_2 D4_3 D4_4 D5_1 D5_2 D5_3 D5_4 R3_1 R3_2 R3_3 R3_4 R8 R14_1 R14_2 R14_3 R14_4 R70 R103 R105 R109 R193_1 R193_2 R193_3 R193_4 R199 R200 R201 R202 R203 R204 R205 R206 R210 R211 R212 R213 R214 R215 R216 R218 R220 R223 R225 R227 R235 R236 R237 R238 R239 R240 R242 R244 R245 R246 R247 R248 R249 R252 R253 R258 R259 R260 U3_1 U3_2 U3_3 U3_4 U25 U26 U27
